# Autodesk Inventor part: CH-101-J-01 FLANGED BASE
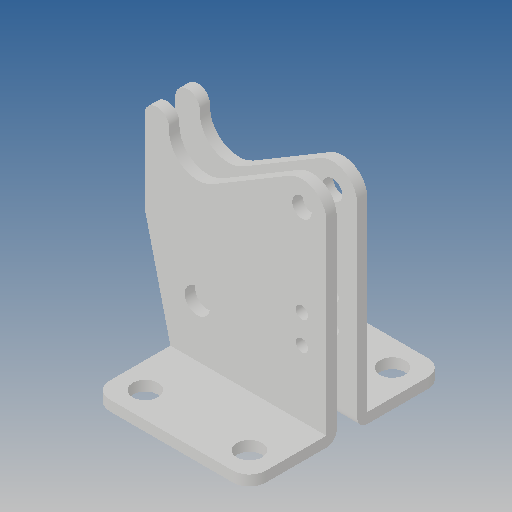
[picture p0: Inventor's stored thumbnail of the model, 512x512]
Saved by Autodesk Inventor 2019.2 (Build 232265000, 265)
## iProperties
Created: 2012-09
Part Number: CH-101-J-01 FLANGED BASE
Material: Ogólny
Document SubType Name: Modeling
Designer: CADENGINEERING4
Density: 1 g/cm^3
Appearance: Domyślna
Author: CADENGINEERING4
Revision Number: ÈÎºÎ
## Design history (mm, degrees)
feature "ÇÐ³ý-À­Éì1"
feature "¾µÏò1"
node "Bryła1"
node "Bryła2"
